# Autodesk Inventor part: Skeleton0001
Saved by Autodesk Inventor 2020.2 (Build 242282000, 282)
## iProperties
_SkeletonDoc: Frame Skeleton File
_Version: 15.0.0
Manager: www.cadconsulting.pl
Company: Fabian Stasiak CAD Consulting
Created: 2015-01
Part Number: Skeleton0001
Material: Ogólny
Document SubType Name: Modeling
Designer: F.Stasiak
Density: 1 g/cm^3
Appearance: Domyślna
Catalog Web Link: www.expertbooks.pl
Author: F.Stasiak
Subject: Zbiór ćwiczeń. Autodesk Inventor 2020. Kurs Professional
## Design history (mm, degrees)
sketch "Szkielet odniesienia"
